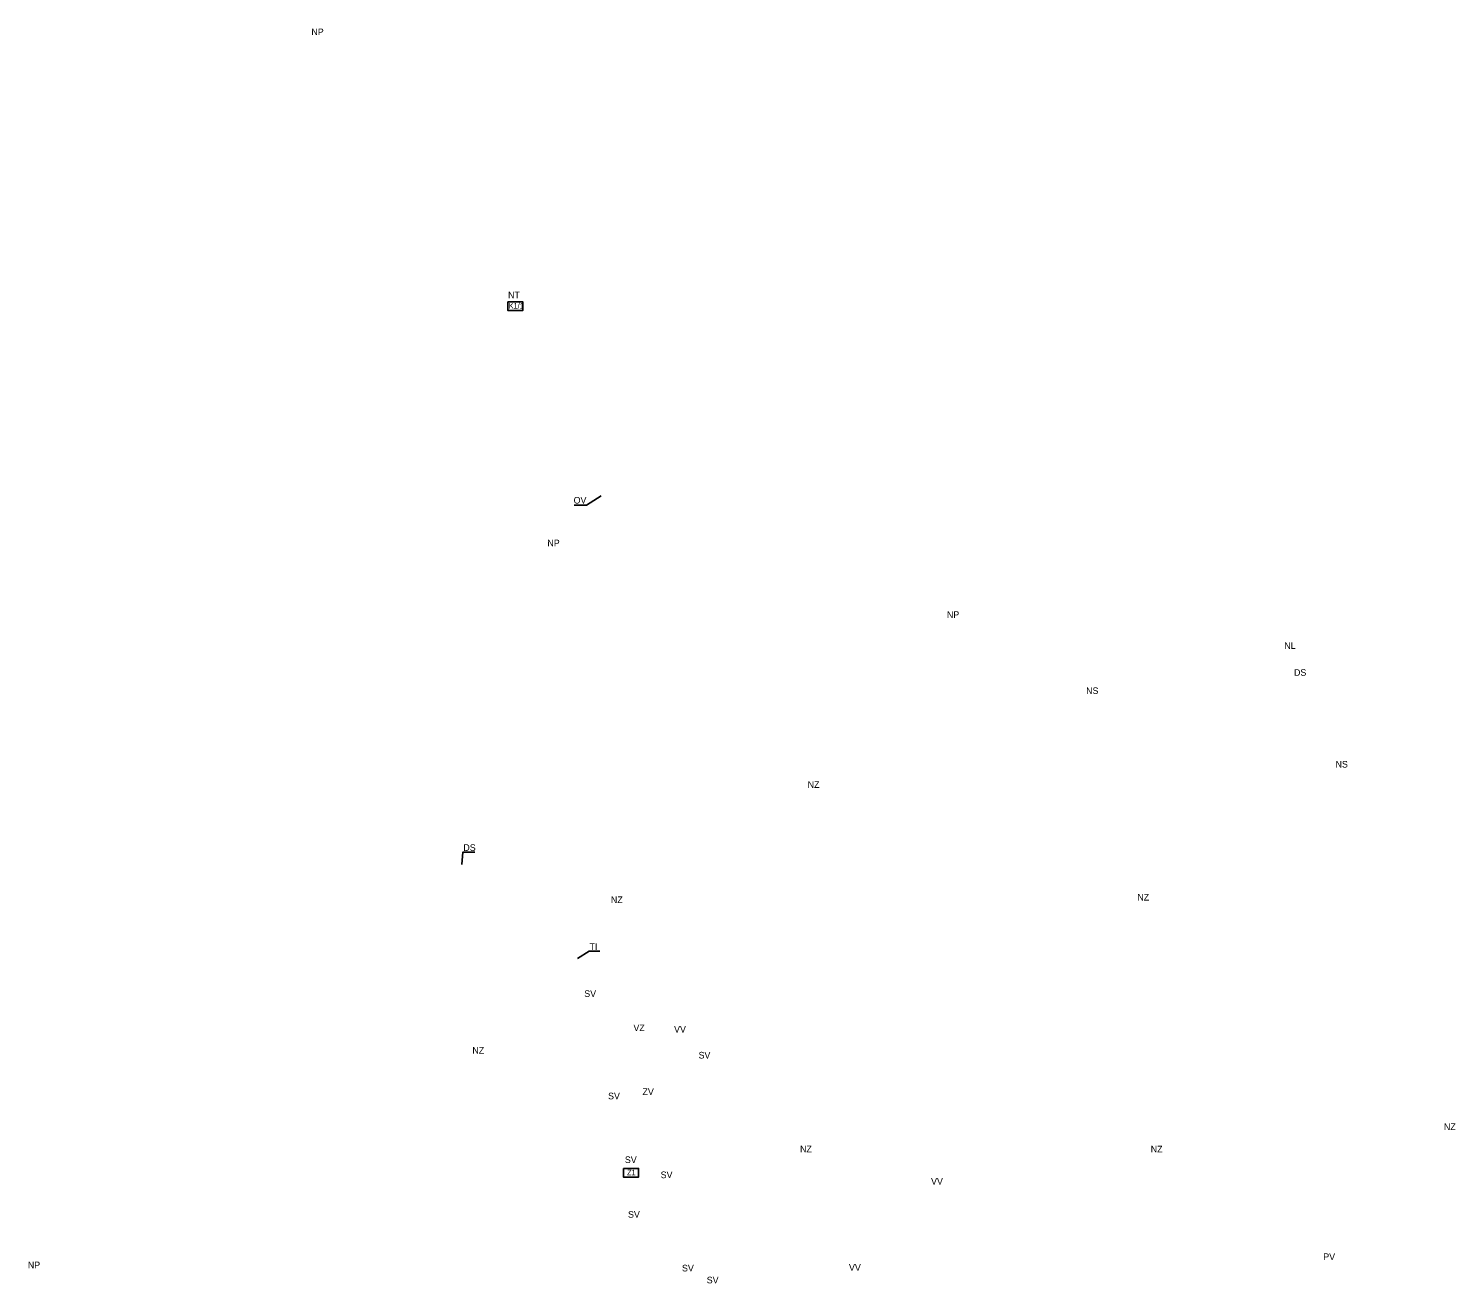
# Model space of a CAD drawing. Extents: x -546576 to -528254, y -1046225 to -1035772.
# Drawn here: x -543708 to -541125, y -1038043 to -1035772 of the extents above; entities that cross this region are included whole.
import ezdxf

# ---------------------------------------------------------------- set-up
doc = ezdxf.new("R2010")
doc.units = 0
for name, color, linetype in [('Vrstva 10', 7, 'Continuous'), ('Vrstva 11', 7, 'Continuous'), ('Vrstva 3', 7, 'Continuous'), ('Vrstva 7', 7, 'Continuous')]:
    doc.layers.add(name, color=color, linetype=linetype)

msp = doc.modelspace()

# ---------------------------------------------------------------- linework, layer by layer
at = {"layer": 'Vrstva 10'}
for points in [[(-542719.9, -1036634.4), (-542697.7, -1036634.4), (-542671, -1036618.1)], [(-542899.6, -1037262.5), (-542921.3, -1037262.5), (-542923.2, -1037284.9)], [(-542673.2, -1037441.8), (-542693, -1037441.8), (-542713.7, -1037454.9)]]:
    msp.add_lwpolyline(points, dxfattribs=at)
at = {"layer": 'Vrstva 3'}
msp.add_lwpolyline([(-542630.8, -1037835), (-542630.8, -1037850.5), (-542603.3, -1037850.5), (-542603.3, -1037835), (-542630.8, -1037835)], dxfattribs=at)
at = {"layer": 'Vrstva 7'}
msp.add_lwpolyline([(-542840.1, -1036266.8), (-542840.1, -1036282.4), (-542812.6, -1036282.4), (-542812.6, -1036266.8), (-542840.1, -1036266.8)], dxfattribs=at)

# ---------------------------------------------------------------- texts
at = {"layer": 'Vrstva 10'}
for s, p in [('NP', (-543195.6, -1035784.2)), ('OV', (-542720.9, -1036631.8)), ('NP', (-542768.4, -1036709.2)), ('NP', (-542045.1, -1036838.7)), ('NL', (-541434.4, -1036894.7)), ('DS', (-541416.8, -1036943.5)), ('NS', (-541793.1, -1036976.5)), ('NS', (-541341.6, -1037109.5)), ('NZ', (-542297.2, -1037146.3)), ('DS', (-542920.5, -1037260.3)), ('NZ', (-542653.4, -1037354.8)), ('NZ', (-541700.4, -1037350.1)), ('TI', (-542692, -1037439.5)), ('SV', (-542701.6, -1037524.6)), ('VZ', (-542612.6, -1037586.5)), ('VV', (-542539, -1037589.1)), ('NZ', (-542904.1, -1037627.3)), ('SV', (-542494.7, -1037636)), ('ZV', (-542596.2, -1037702.1)), ('SV', (-542658.5, -1037709.8)), ('NZ', (-541145.4, -1037765.4)), ('NZ', (-542310.9, -1037805.6)), ('NZ', (-541676.1, -1037806)), ('SV', (-542563.3, -1037852.5)), ('VV', (-542073.8, -1037864.3)), ('SV', (-542622.4, -1037924.1)), ('PV', (-541363.8, -1038000.7)), ('NP', (-543708.9, -1038015.6)), ('SV', (-542524.7, -1038021.3)), ('VV', (-542222.4, -1038020.1))]:
    msp.add_text(s, height=12, dxfattribs=at).set_placement(p)
at = {"layer": 'Vrstva 11'}
for s, p in [('NT', (-542839.5, -1036260.4)), ('SV', (-542628.1, -1037825.2)), ('SV', (-542479.9, -1038042.9))]:
    msp.add_text(s, height=12, dxfattribs=at).set_placement(p)
at = {"layer": 'Vrstva 3'}
msp.add_text('Z1', height=10, dxfattribs=at).set_placement((-542624.1, -1037847.1))
at = {"layer": 'Vrstva 7'}
msp.add_text('K1/1', height=10, dxfattribs=at).set_placement((-542838.5, -1036278.9))

doc.saveas('drawing.dxf')
